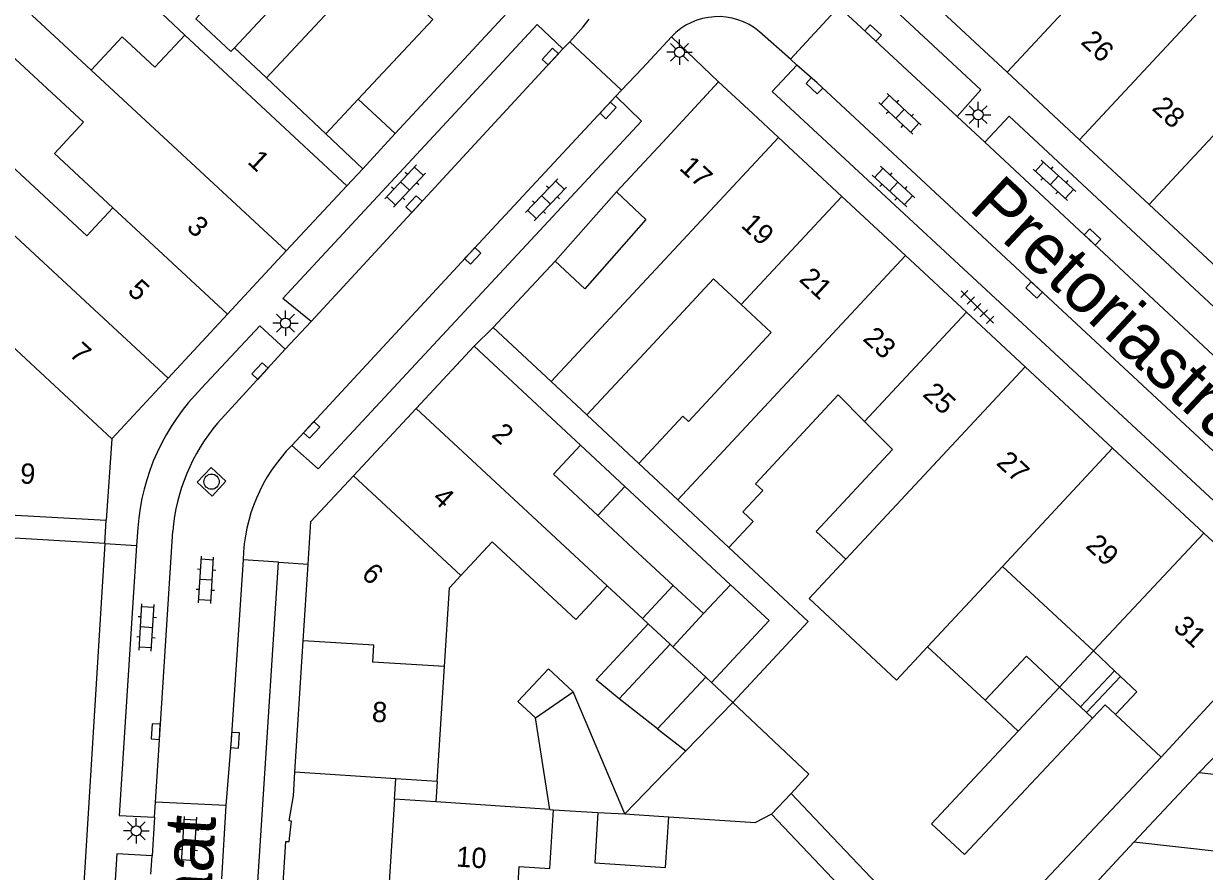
# Model space of a CAD drawing. Extents: x 132994 to 136000, y 393499 to 395512.
# Drawn here: x 133057.6 to 133115.8, y 395265.4 to 395307.2 of the extents above; entities that cross this region are included whole.
import ezdxf

# ---------------------------------------------------------------- set-up
doc = ezdxf.new("R2010")
doc.units = 0
for name, color, linetype in [('gg-afsc-erfafscheiding', 7, 'Continuous'), ('gg-afsc-muur', 7, 'Continuous'), ('gg-anno-huisnummerreeks BGT', 7, 'Continuous'), ('gg-anno-openbare ruimte label', 7, 'Continuous'), ('gg-bbg-bijgebouw', 7, 'Continuous'), ('gg-bbg-gedigitaliseerde bebouwing', 7, 'Continuous'), ('gg-bbg-gedigitaliseerde bijgebouw', 7, 'Continuous'), ('gg-bbg-hoofdgebouw', 7, 'Continuous'), ('gg-bbg-luifel en loopbrug', 7, 'Continuous'), ('gg-bbg-tussenscheiding', 7, 'Continuous'), ('gg-knt-verharding', 7, 'Continuous'), ('gt-grn-weggrens', 7, 'Continuous'), ('gt-symb-klinker verharding', 7, 'Continuous'), ('gt-symb-kolk', 7, 'Continuous'), ('gt-symb-lichtmast', 7, 'Continuous'), ('gt-symb-rioolschacht', 7, 'Continuous'), ('gt-symb-tegel verharding', 7, 'Continuous')]:
    doc.layers.add(name, color=color, linetype=linetype)

# ---------------------------------------------------------------- blocks, each defined once
blk = doc.blocks.new('gt0-KOLK')
at = {"layer": 'gt-symb-kolk'}
blk.add_lwpolyline([(0, 0), (0.375, 0), (0.375, 0.4), (-0.375, 0.4), (-0.375, 0), (0, 0)], dxfattribs=at)
blk = doc.blocks.new('gt0-LMAST')
at = {"layer": 'gt-symb-lichtmast'}
for p, q in [((-0.005, 0.246), (-0.005, 0.621)), ((-0.182, 0.173), (-0.447, 0.438)), ((0.172, 0.173), (0.437, 0.438)), ((-0.255, -0.004), (-0.63, -0.004)), ((-0.182, -0.181), (-0.447, -0.446)), ((-0.005, -0.254), (-0.005, -0.629)), ((0.437, -0.446), (0.172, -0.181)), ((0.245, -0.004), (0.62, -0.004))]:
    blk.add_line(p, q, dxfattribs=at)
blk.add_circle((-0.005, -0.004), 0.25, dxfattribs=at)
blk = doc.blocks.new('gt0-KL1')
at = {"layer": 'gt-symb-klinker verharding'}
for p, q in [((-1.15, 0.3), (1.15, 0.3)), ((-1, -0.3), (-1, 0.3)), ((-0.5, 0.3), (-0.5, 0.45)), ((0, -0.3), (0, 0.3)), ((0.5, 0.3), (0.5, 0.45)), ((1, -0.3), (1, 0.3)), ((-1.15, -0.3), (1.15, -0.3)), ((-0.5, -0.45), (-0.5, -0.3)), ((0.5, -0.45), (0.5, -0.3))]:
    blk.add_line(p, q, dxfattribs=at)
blk = doc.blocks.new('gt0-RS')
at = {"layer": 'gt-symb-rioolschacht'}
blk.add_lwpolyline([(-0.5, -0.5), (0.5, -0.5), (0.5, 0.5), (-0.5, 0.5)], close=True, dxfattribs=at)
blk.add_circle((0, 0), 0.375, dxfattribs=at)
blk = doc.blocks.new('gt0-TEG1')
at = {"layer": 'gt-symb-tegel verharding'}
for p, q in [((-1.125, 0), (1.125, 0)), ((-0.9, -0.25), (-0.9, 0.25)), ((-0.45, -0.25), (-0.45, 0.25)), ((0, -0.25), (0, 0.25)), ((0.45, -0.25), (0.45, 0.25)), ((0.9, -0.25), (0.9, 0.25))]:
    blk.add_line(p, q, dxfattribs=at)

msp = doc.modelspace()

# ---------------------------------------------------------------- linework, layer by layer
at = {"layer": 'gg-afsc-erfafscheiding'}
for p, q in [((133065.525, 395306.589), (133061.054, 395310.814)), ((133072.478, 395301.716), (133069.548, 395304.477)), ((133074.298, 395300), (133073.51, 395299.16)), ((133087.89, 395285.475), (133085.328, 395287.867)), ((133087.215, 395284.332), (133092.41, 395279.492)), ((133113.634, 395270.992), (133105.118, 395261.98)), ((133115.495, 395270.24), (133112.283, 395266.799)), ((133095.398, 395269.207), (133097.441, 395267.057)), ((133100.886, 395261.397), (133094.441, 395268.179)), ((133101.126, 395263.177), (133097.441, 395267.057))]:
    msp.add_line(p, q, dxfattribs=at)
msp.add_lwpolyline([(133092.53, 395273.682), (133096.242, 395277.675), (133092.336, 395281.335)], dxfattribs=at)
at = {"layer": 'gg-afsc-muur'}
for p, q in [((133083.78, 395295.45), (133086.8, 395298.86)), ((133061.589, 395281.532), (133055.547, 395281.872))]:
    msp.add_line(p, q, dxfattribs=at)
at = {"layer": 'gg-bbg-bijgebouw'}
msp.add_line((133083.513, 395268.415), (133082.799, 395272.939), dxfattribs=at)
at = {"layer": 'gg-bbg-gedigitaliseerde bebouwing'}
for p, q in [((133057.992, 395307.573), (133060.92, 395304.858)), ((133073.51, 395299.16), (133065.525, 395306.589)), ((133067.973, 395305.961), (133069.548, 395304.477)), ((133080.72, 395292.18), (133083.574, 395289.509)), ((133085.025, 395286.373), (133079.78, 395291.26)), ((133085.328, 395287.867), (133088.383, 395291.131)), ((133083.574, 395289.509), (133085.328, 395287.867)), ((133089.824, 395283.674), (133087.89, 395285.475)), ((133092.336, 395281.335), (133089.824, 395283.674)), ((133087.856, 395281.071), (133085.881, 395282.907)), ((133089.592, 395279.458), (133087.856, 395281.071)), ((133102.124, 395276.436), (133105.81, 395280.397)), ((133105.81, 395280.397), (133110.292, 395276.226)), ((133079.128, 395279.949), (133078.569, 395279.347)), ((133078.32, 395275.455), (133078.569, 395279.347)), ((133088.074, 395277.824), (133086.338, 395279.438)), ((133088.074, 395277.824), (133089.592, 395279.458)), ((133111.331, 395275.253), (133110.292, 395276.226)), ((133077.958, 395269.792), (133078.32, 395275.455)), ((133111.627, 395274.976), (133111.331, 395275.253)), ((133113.634, 395270.992), (133111.385, 395273.1)), ((133083.509, 395265.499), (133083.694, 395268.404))]:
    msp.add_line(p, q, dxfattribs=at)
for points in [[(133069.548, 395304.477), (133074.79, 395310.102), (133076.324, 395308.672)], [(133076.324, 395308.672), (133077.741, 395307.351), (133074.07, 395303.43)], [(133066.248, 395307.587), (133066.07, 395307.395), (133067.804, 395305.78), (133067.973, 395305.961)], [(133061.988, 395298.073), (133059.104, 395300.747), (133060.534, 395302.289), (133056.062, 395306.437)], [(133065.525, 395306.589), (133064.058, 395305.007), (133062.445, 395306.503), (133060.92, 395304.858)], [(133061.988, 395298.073), (133060.711, 395296.696), (133053.905, 395303.009), (133052.253, 395301.228), (133054.937, 395298.74)], [(133088.383, 395291.131), (133091.583, 395294.567), (133092.942, 395293.302)], [(133092.942, 395293.302), (133094.423, 395291.923), (133090.344, 395287.542)], [(133099.023, 395287.545), (133097.724, 395288.85), (133093.645, 395284.469), (133094.001, 395284.137), (133093.022, 395283.086), (133093.528, 395282.615), (133092.336, 395281.335)], [(133087.89, 395285.475), (133090.061, 395287.806), (133090.344, 395287.542)], [(133098.1, 395280.755), (133096.636, 395282.118), (133100.4, 395286.161), (133099.023, 395287.545)], [(133085.881, 395282.907), (133083.694, 395284.94), (133085.025, 395286.373)], [(133079.128, 395279.949), (133080.676, 395281.615), (133084.799, 395277.782), (133086.338, 395279.438)], [(133098.1, 395280.755), (133096.287, 395278.806), (133100.598, 395274.794), (133102.124, 395276.436)], [(133111.385, 395273.1), (133112.434, 395274.22), (133111.627, 395274.976)], [(133081.831, 395262.808), (133082.008, 395265.595), (133083.509, 395265.499)]]:
    msp.add_lwpolyline(points, dxfattribs=at)
at = {"layer": 'gg-bbg-gedigitaliseerde bijgebouw'}
for p, q in [((133092.41, 395279.492), (133091.087, 395278.068)), ((133091.087, 395278.068), (133089.569, 395276.436)), ((133086.926, 395273.865), (133089.433, 395276.562)), ((133089.433, 395276.562), (133089.569, 395276.436)), ((133088.825, 395272.383), (133091.191, 395274.928)), ((133091.191, 395274.928), (133091.47, 395274.668)), ((133108.619, 395274.44), (133109.658, 395273.466)), ((133087.201, 395268.192), (133084.664, 395274.209)), ((133088.825, 395272.383), (133086.926, 395273.865)), ((133104.96, 395273.799), (133106.589, 395272.273)), ((133090.216, 395271.298), (133092.53, 395273.682)), ((133109.658, 395273.466), (133109.953, 395273.19)), ((133109.953, 395273.19), (133110.248, 395272.914)), ((133102.317, 395267.713), (133106.589, 395272.273)), ((133117.699, 395272.52), (133115.495, 395270.24)), ((133087.201, 395268.192), (133090.216, 395271.298)), ((133115.495, 395270.24), (133125.921, 395269.031)), ((133094.441, 395268.179), (133095.398, 395269.207)), ((133083.694, 395268.404), (133085.88, 395268.272)), ((133089.374, 395268.051), (133093.639, 395267.776)), ((133094.441, 395268.179), (133093.639, 395267.776)), ((133112.283, 395266.799), (133107.052, 395261.194))]:
    msp.add_line(p, q, dxfattribs=at)
for points in [[(133091.47, 395274.668), (133094.311, 395277.725), (133092.41, 395279.492)], [(133108.619, 395274.44), (133106.99, 395275.966), (133104.96, 395273.799)], [(133082.799, 395272.939), (133081.944, 395273.734), (133083.442, 395275.345), (133084.664, 395274.209)], [(133092.53, 395273.682), (133096.272, 395270.147), (133095.398, 395269.207)], [(133110.248, 395272.914), (133103.946, 395266.187), (133102.317, 395267.713)], [(133085.88, 395268.272), (133085.722, 395265.78), (133089.215, 395265.558), (133089.374, 395268.051)], [(133116.348, 395263.324), (133116.683, 395266.305), (133112.283, 395266.799)]]:
    msp.add_lwpolyline(points, dxfattribs=at)
at = {"layer": 'gg-bbg-hoofdgebouw'}
for p, q in [((133081.82, 395308.124), (133075.9, 395301.73)), ((133102.392, 395308.142), (133106.037, 395304.752)), ((133106.037, 395304.752), (133109.612, 395301.427)), ((133091.83, 395304.29), (133089.073, 395301.314)), ((133093.508, 395302.728), (133091.83, 395304.29)), ((133074.07, 395303.43), (133075.9, 395301.73)), ((133094.779, 395301.545), (133093.508, 395302.728)), ((133089.073, 395301.314), (133086.8, 395298.86)), ((133097.906, 395298.634), (133094.779, 395301.545)), ((133109.612, 395301.427), (133113.042, 395298.237)), ((133073.51, 395299.16), (133070.529, 395295.947)), ((133101.038, 395295.718), (133097.906, 395298.634)), ((133113.042, 395298.237), (133116.873, 395294.673)), ((133070.529, 395295.947), (133067.639, 395292.832)), ((133083.78, 395295.45), (133080.72, 395292.18)), ((133104.034, 395292.928), (133101.038, 395295.718)), ((133106.926, 395290.236), (133104.034, 395292.928)), ((133067.639, 395292.832), (133064.711, 395289.676)), ((133076.925, 395288.188), (133079.78, 395291.26)), ((133111.234, 395286.226), (133106.926, 395290.236)), ((133064.711, 395289.676), (133061.94, 395286.69)), ((133073.837, 395284.867), (133076.925, 395288.188)), ((133061.94, 395286.69), (133061.663, 395282.681)), ((133115.735, 395282.036), (133111.234, 395286.226)), ((133055.64, 395283.001), (133061.663, 395282.681)), ((133120.07, 395278), (133115.735, 395282.036)), ((133071.364, 395276.732), (133071.606, 395280.509)), ((133120.07, 395278), (133113.634, 395270.992)), ((133070.95, 395270.26), (133071.364, 395276.732)), ((133075.924, 395269.928), (133070.95, 395270.26)), ((133077.958, 395269.792), (133075.924, 395269.928)), ((133075.86, 395268.92), (133075.497, 395263.22)), ((133077.894, 395268.786), (133075.86, 395268.92)), ((133083.513, 395268.415), (133077.894, 395268.786))]:
    msp.add_line(p, q, dxfattribs=at)
for points in [[(133086.8, 395298.86), (133088.25, 395297.49), (133085.24, 395294.08), (133083.78, 395295.45)], [(133071.606, 395280.509), (133071.74, 395282.61), (133073.837, 395284.867)]]:
    msp.add_lwpolyline(points, dxfattribs=at)
at = {"layer": 'gg-bbg-luifel en loopbrug'}
for p, q in [((133074.07, 395303.43), (133072.478, 395301.716)), ((133074.298, 395300), (133072.478, 395301.716)), ((133075.9, 395301.73), (133074.298, 395300)), ((133085.025, 395286.373), (133087.215, 395284.332)), ((133085.881, 395282.907), (133087.215, 395284.332)), ((133089.592, 395279.458), (133091.087, 395278.068)), ((133088.074, 395277.824), (133088.36, 395277.558)), ((133089.433, 395276.562), (133088.36, 395277.558)), ((133104.96, 395273.799), (133102.124, 395276.436)), ((133108.619, 395274.44), (133110.292, 395276.226)), ((133111.331, 395275.253), (133109.658, 395273.466)), ((133109.953, 395273.19), (133111.627, 395274.976)), ((133091.47, 395274.668), (133092.53, 395273.682)), ((133088.825, 395272.383), (133090.216, 395271.298)), ((133075.86, 395268.92), (133075.924, 395269.928)), ((133077.958, 395269.792), (133077.894, 395268.786))]:
    msp.add_line(p, q, dxfattribs=at)
for points in [[(133086.926, 395273.865), (133085.8, 395274.804), (133088.36, 395277.558)], [(133110.248, 395272.914), (133110.872, 395273.58), (133111.385, 395273.1)]]:
    msp.add_lwpolyline(points, dxfattribs=at)
at = {"layer": 'gg-bbg-tussenscheiding'}
for p, q in [((133078.205, 395316.941), (133067.973, 395305.961)), ((133106.037, 395304.752), (133113.089, 395312.333)), ((133109.612, 395301.427), (133118.809, 395311.315)), ((133070.529, 395295.947), (133060.92, 395304.858)), ((133113.042, 395298.237), (133118.016, 395303.586)), ((133083.574, 395289.509), (133094.779, 395301.545)), ((133064.711, 395289.676), (133054.937, 395298.74)), ((133092.942, 395293.302), (133097.906, 395298.634)), ((133061.988, 395298.073), (133067.639, 395292.832)), ((133101.038, 395295.718), (133089.824, 395283.674)), ((133099.023, 395287.545), (133104.034, 395292.928)), ((133106.926, 395290.236), (133098.1, 395280.755)), ((133076.925, 395288.188), (133086.338, 395279.438)), ((133105.81, 395280.397), (133111.234, 395286.226)), ((133079.128, 395279.949), (133073.837, 395284.867)), ((133115.735, 395282.036), (133110.292, 395276.226)), ((133089.569, 395276.436), (133091.191, 395274.928)), ((133108.619, 395274.44), (133106.589, 395272.273)), ((133082.799, 395272.939), (133084.664, 395274.209)), ((133083.513, 395268.415), (133083.694, 395268.404)), ((133085.88, 395268.272), (133087.201, 395268.192))]:
    msp.add_line(p, q, dxfattribs=at)
for points in [[(133061.94, 395286.69), (133056.274, 395291.945), (133052.534, 395295.066)], [(133078.32, 395275.455), (133074.797, 395275.683), (133074.85, 395276.508), (133071.364, 395276.732)], [(133087.201, 395268.192), (133087.662, 395268.162), (133089.374, 395268.051)]]:
    msp.add_lwpolyline(points, dxfattribs=at)
at = {"layer": 'gg-knt-verharding'}
for p, q in [((133097.748, 395307.979), (133095.368, 395305.403)), ((133097.748, 395307.979), (133103.584, 395302.567)), ((133082.886, 395307.101), (133084.149, 395305.906)), ((133095.368, 395305.403), (133093.838, 395306.749)), ((133071.761, 395292.464), (133084.149, 395305.906)), ((133084.149, 395305.906), (133084.498, 395306.254)), ((133087.044, 395303.876), (133084.498, 395306.254)), ((133094.473, 395303.804), (133095.685, 395305.11)), ((133095.685, 395305.11), (133095.368, 395305.403)), ((133087.044, 395303.876), (133086.766, 395303.579)), ((133086.766, 395303.579), (133088.033, 395302.343)), ((133103.584, 395302.567), (133104.948, 395301.312)), ((133071.761, 395292.464), (133070.477, 395291.106)), ((133067.144, 395287.461), (133070.477, 395291.106)), ((133063.213, 395282.298), (133063.156, 395281.429)), ((133064.082, 395268.769), (133064.939, 395282.135)), ((133070.146, 395280.604), (133068.403, 395280.718)), ((133064.036, 395268.027), (133064.082, 395268.769)), ((133067.551, 395268.611), (133064.082, 395268.769)), ((133067.551, 395268.611), (133067.337, 395265.003)), ((133064.036, 395268.027), (133063.918, 395266.137)), ((133063.863, 395265.224), (133063.918, 395266.137))]:
    msp.add_line(p, q, dxfattribs=at)
for points in [[(133090.599, 395314.589), (133091.877, 395315.887), (133104.751, 395303.886), (133103.584, 395302.567)], [(133071.761, 395292.464), (133070.364, 395293.61), (133082.886, 395307.101)], [(133084.498, 395306.254), (133085.151, 395307), (133085.443, 395307.376)], [(133089.505, 395306.495), (133088.057, 395304.937), (133087.044, 395303.876)], [(133119.464, 395283.053), (133096.68, 395304.233), (133095.685, 395305.11)], [(133086.766, 395303.579), (133079.564, 395295.841), (133070.799, 395286.358)], [(133119.464, 395283.053), (133118.244, 395281.758), (133094.473, 395303.804)], [(133088.033, 395302.343), (133072.098, 395285.199), (133070.799, 395286.358)], [(133104.948, 395301.312), (133106.14, 395302.591), (133122.962, 395286.917)], [(133104.948, 395301.312), (133119.878, 395287.377), (133121.593, 395285.853)], [(133070.477, 395291.106), (133069.227, 395292.262), (133066.353, 395289.178)], [(133061.589, 395281.532), (133059.955, 395254.921), (133060.204, 395254.905), (133059.754, 395247.702), (133059.505, 395247.717), (133059.433, 395246.518), (133059.677, 395246.494), (133059.542, 395244.735), (133059.292, 395244.754), (133059.248, 395243.22), (133059.454, 395243.182), (133059.236, 395239.609), (133058.986, 395239.624), (133058.979, 395239.513)], [(133063.156, 395281.429), (133062.29, 395268.123), (133064.036, 395268.027)], [(133068.403, 395280.718), (133067.807, 395271.84), (133067.551, 395268.611)], [(133064.395, 395218.4), (133066.115, 395218.323), (133070.146, 395280.604)], [(133068.55, 395232.29), (133069.452, 395247.911), (133069.25, 395247.971), (133069.743, 395255.147), (133069.8, 395255.18), (133069.979, 395256.327), (133069.875, 395256.295), (133069.826, 395256.676), (133069.931, 395258.161), (133070.03, 395258.154), (133070.043, 395258.434), (133070.198, 395258.499), (133070.24, 395259.512), (133070.131, 395259.512), (133070.142, 395259.663), (133070.055, 395259.66), (133070.512, 395266.835), (133070.679, 395266.842), (133070.789, 395267.844), (133070.668, 395267.859), (133070.877, 395269.079), (133070.95, 395270.26)], [(133063.918, 395266.137), (133062.188, 395266.233), (133060.399, 395237.872), (133062.133, 395237.758)]]:
    msp.add_lwpolyline(points, dxfattribs=at)
for centre, radius, start, end in [((133091.804, 395304.36), 3.138, 49.59573, 137.11393), ((133074.081, 395281.494), 10.898, 135.16529, 175.77124), ((133074.332, 395281.366), 9.424, 139.70231, 175.31791), ((133076.667, 395280.536), 8.266, 135.2277, 178.73853)]:
    msp.add_arc(centre, radius, start, end, dxfattribs=at)
at = {"layer": 'gt-grn-weggrens'}
for p, q in [((133091.83, 395304.29), (133089.505, 395306.495)), ((133080.72, 395292.18), (133079.78, 395291.26)), ((133061.589, 395281.532), (133061.663, 395282.681)), ((133061.589, 395281.532), (133063.156, 395281.429)), ((133070.146, 395280.604), (133071.606, 395280.509))]:
    msp.add_line(p, q, dxfattribs=at)

# ---------------------------------------------------------------- block references
at = {"layer": 'gt-symb-klinker verharding'}
for p, rotation in [((133100.763, 395302.707), -42.89091026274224), ((133108.372, 395299.424), -42.4471018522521), ((133076.381, 395299.145), 46.9442303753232), ((133100.45, 395299.123), -42.28524834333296), ((133083.326, 395298.465), 46.13442163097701), ((133066.578, 395279.73), 86.3879250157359), ((133063.647, 395277.391), 86.3879250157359), ((133065.743, 395266.907), 86.3879250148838)]:
    msp.add_blockref('gt0-KL1', p, dxfattribs=dict(at, rotation=rotation))
at = {"layer": 'gt-symb-kolk'}
for p, rotation in [((133099.305, 395306.537), -42.7709286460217), ((133083.685, 395305.391), 47.31004222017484), ((133096.68, 395304.233), 137.0671032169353), ((133086.24, 395303.013), -132.85190841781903), ((133076.972, 395298.118), 47.31004222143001), ((133110.111, 395296.488), -43.05576962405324), ((133079.564, 395295.841), -132.9328967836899), ((133107.506, 395294.169), 137.06710321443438), ((133069.375, 395289.888), 47.39100385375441), ((133071.63, 395287.26), -132.77092864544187), ((133064.297, 395272.246), 87.0203262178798), ((133067.807, 395271.84), -93.84074707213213)]:
    msp.add_blockref('gt0-KOLK', p, dxfattribs=dict(at, rotation=rotation))
at = {"layer": 'gt-symb-lichtmast'}
for p in [(133089.907, 395305.742), (133104.615, 395302.668), (133070.498, 395292.39), (133063.146, 395267.369)]:
    msp.add_blockref('gt0-LMAST', p, dxfattribs=at)
at = {"layer": 'gt-symb-rioolschacht', "rotation": 47.26795453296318}
msp.add_blockref('gt0-RS', (133066.85, 395284.573), dxfattribs=at)
at = {"layer": 'gt-symb-tegel verharding', "rotation": -45.04049171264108}
msp.add_blockref('gt0-TEG1', (133104.572, 395293.187), dxfattribs=at)

# ---------------------------------------------------------------- texts
at = {"layer": 'gg-anno-huisnummerreeks BGT'}
for s, rotation, p in [('26', 317.1, (133109.626, 395306.194)), ('28', 317.1, (133113.129, 395302.936)), ('1', 317.1, (133068.574, 395300.292)), ('17', 317.1, (133089.845, 395299.989)), ('3', 317.1, (133065.567, 395297.051)), ('19', 317.1, (133092.879, 395297.164)), ('21', 317.1, (133095.745, 395294.496)), ('5', 317.1, (133062.658, 395293.915)), ('23', 317.1, (133098.886, 395291.572)), ('7', 317.1, (133059.781, 395290.815)), ('25', 317.1, (133101.83, 395288.83)), ('2', 317.1, (133080.595, 395286.832)), ('27', 317.1, (133105.46, 395285.451)), ('9', 356, (133057.389, 395284.495)), ('4', 317.1, (133077.673, 395283.689)), ('29', 317.1, (133109.861, 395281.355)), ('6', 317.1, (133074.182, 395279.932)), ('31', 317.1, (133114.175, 395277.339)), ('8', 356.3, (133074.727, 395272.744)), ('10', 356.3, (133078.878, 395265.603))]:
    msp.add_text(s, height=1, rotation=rotation, dxfattribs=at).set_placement(p)
at = {"layer": 'gg-anno-openbare ruimte label'}
for s, rotation, p in [('Pretoriastraat', 316.9, (133104.096, 395298.006)), ('Zandrivierstraat', 86.4, (133065.603, 395244.862))]:
    msp.add_text(s, height=2.5, rotation=rotation, dxfattribs=at).set_placement(p)

doc.saveas('drawing.dxf')
